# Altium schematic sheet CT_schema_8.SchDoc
size 308 x 210 mm
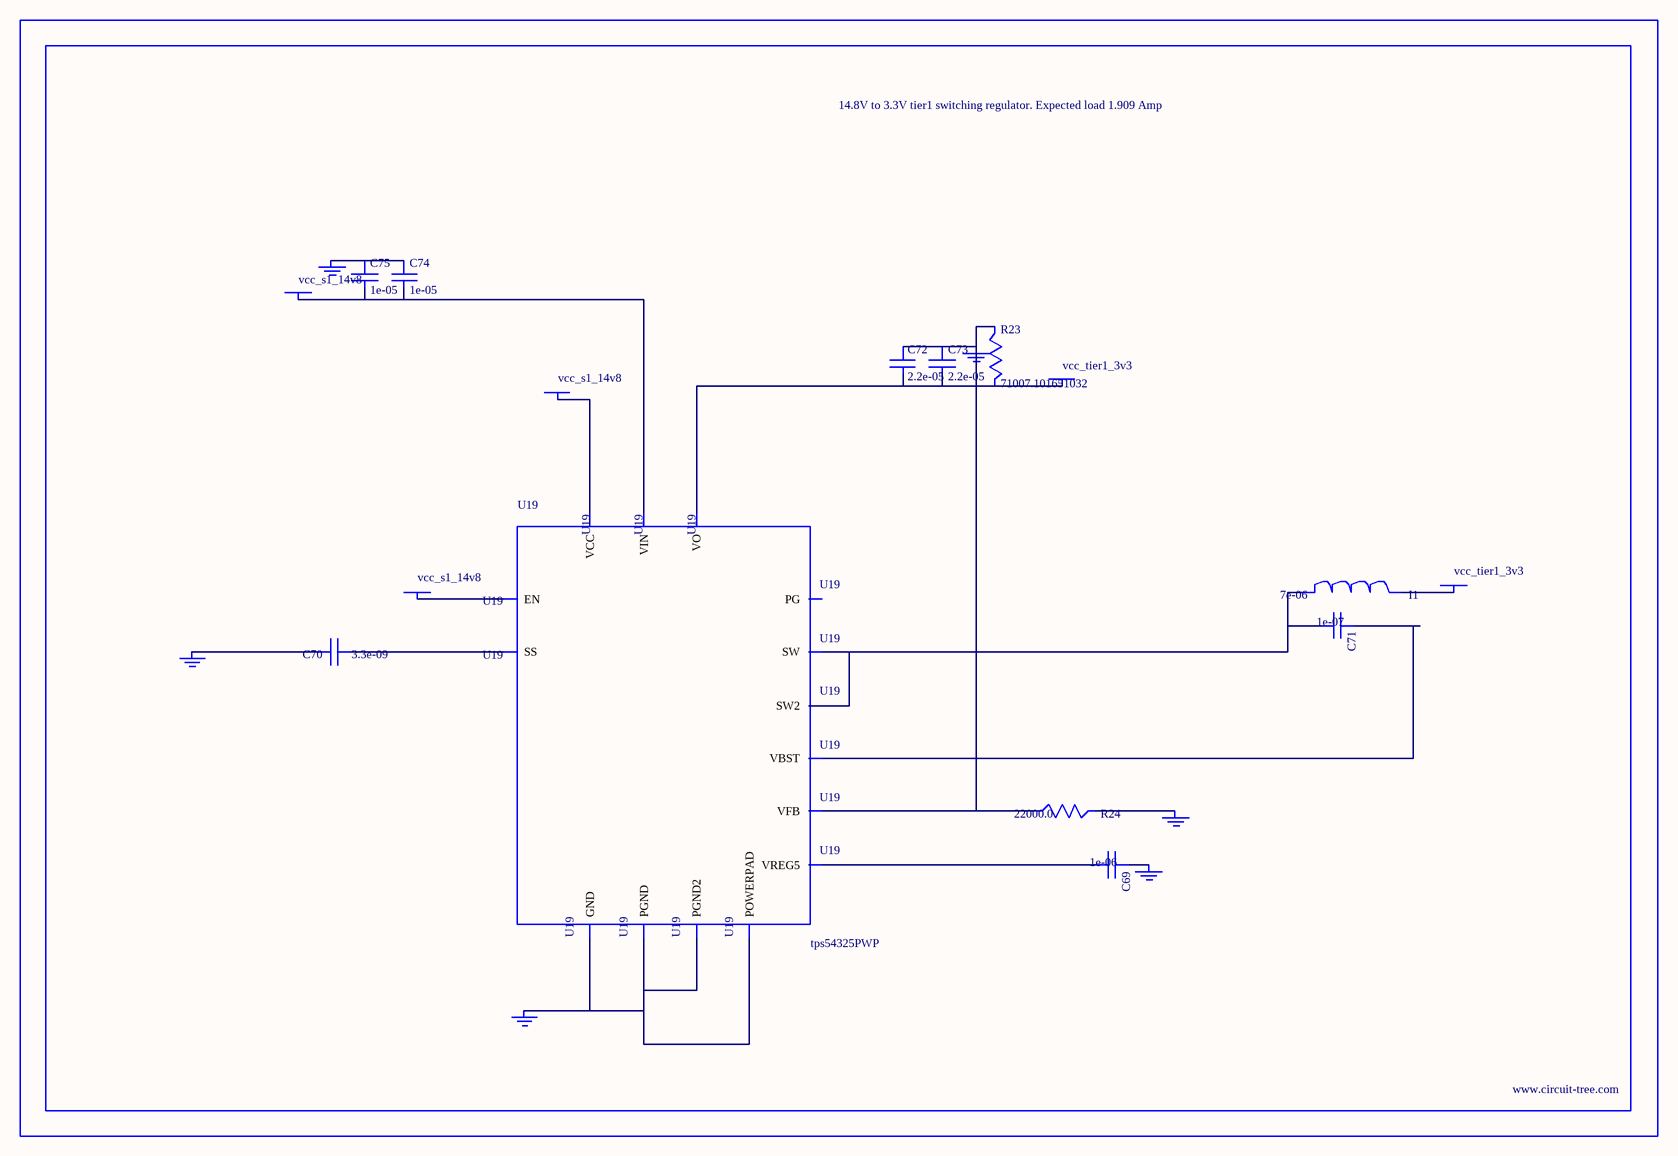
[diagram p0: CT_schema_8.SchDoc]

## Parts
BORDER7  (no value)
C69  1e-06  [C0603]
C70  3.3e-09  [C0402]
C71  1e-07  [C0402]
C72  2.2e-05  [C1210]
C73  2.2e-05  [C1210]
C74  1e-05  [C1206]
C75  1e-05  [C1206]
GND_INSTANCE_7_0  (no value)
GND_INSTANCE_7_1  (no value)
GND_INSTANCE_7_2  (no value)
GND_INSTANCE_7_3  (no value)
GND_INSTANCE_7_4  (no value)
GND_INSTANCE_7_5  (no value)
I1  7e-06  [DR1040]
POWER_INSTANCE_7_0  vcc_tier1_3v3
POWER_INSTANCE_7_1  vcc_s1_14v8
POWER_INSTANCE_7_2  vcc_tier1_3v3
POWER_INSTANCE_7_3  vcc_s1_14v8
POWER_INSTANCE_7_4  vcc_s1_14v8
R23  71007.101651032  [R0603]
R24  22000.0  [R0603]
U19  tps54325PWP  [HTSSOP14]

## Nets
NetC69_1: C69.1 GND_INSTANCE_7_2.0(GND)
NetC69_2: C69.2 U19.3(VREG5)
NetC70_1: C70.1 U19.4(SS)
NetC70_2: C70.2 GND_INSTANCE_7_3.0(GND)
NetC71_1: C71.1 U19.12(VBST)
NetC71_2: C71.2 I1.1 U19.10(SW) U19.11(SW2)
NetC72_1: C72.1 C73.1 GND_INSTANCE_7_0.0(GND) R23.1 R24.1 U19.2(VFB)
NetC72_2: C72.2 C73.2 POWER_INSTANCE_7_0.0(PWR) R23.2 U19.1(VO)
NetC74_1: C74.1 C75.1 GND_INSTANCE_7_5.0(GND)
NetC74_2: C74.2 C75.2 POWER_INSTANCE_7_3.0(PWR) U19.13(VIN)
NetGND_INSTANCE_7_1_0: GND_INSTANCE_7_1.0(GND) R24.2
NetGND_INSTANCE_7_4_0: GND_INSTANCE_7_4.0(GND) U19.5(GND) U19.8(PGND) U19.9(PGND2) U19.15(POWERPAD)
NetI1_2: I1.2 POWER_INSTANCE_7_2.0(PWR)
NetPOWER_INSTANCE_7_1_0: POWER_INSTANCE_7_1.0(PWR) U19.7(EN)
NetPOWER_INSTANCE_7_4_0: POWER_INSTANCE_7_4.0(PWR) U19.14(VCC)

Not connected (* = marked no-connect by the designer): U19 6(PG)

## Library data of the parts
BORDER7 = BORDER_PAGE7
C69 = C0603C105K3RACTU
C70 = C0402C332K3RAC
C71 = C0402C104K3RACTU
C72 C73 = GRM32ER61E226ME15L
C74 C75 = C1206C106K3RACTU
GND_INSTANCE_7_0-GND_INSTANCE_7_5 = GND
I1 = DR1040-7R0-R
POWER_INSTANCE_7_0-POWER_INSTANCE_7_4 = PWR
R23 = R23
R24 = RC0603JR-0722KL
